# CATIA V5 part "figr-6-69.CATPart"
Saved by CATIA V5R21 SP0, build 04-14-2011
Part number: Part1
Bounding box of the stored display mesh (mm): x -44.666 to 106.759, y -69.79 to 69.79, z 0 to 74
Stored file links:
  D:\CATIA V5R21 E-RESOURCES\CATIA-V5R21\catia-v5r21-prt\c06-catia-v5r21-prt\c06-catia-v5r21-figr-6-69.CATPart
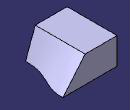
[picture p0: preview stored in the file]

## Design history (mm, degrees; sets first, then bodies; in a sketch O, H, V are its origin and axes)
Body1 (main body)
  Sketch1 on xy-plane, origin (0, 0, 0), H (1, 0, 0), V (0, 1, 0)
    line L1 (44.6658, 69.7903) -> (44.6658, -69.7903)
    line L2 (44.6658, -69.7903) -> (-44.6658, -69.7903)
    line L3 (-44.6658, -69.7903) -> (-44.6658, 69.7903)
    line L4 (-44.6658, 69.7903) -> (44.6658, 69.7903)
    vertical: L1 V, L3 V
    horizontal: L2 H, L4 H
    equidistance: L1 L3 O, L2 L4 O
  Pad1: profile Sketch1, direction (0, 0, 1), length 74
  Draft1: Angle 30, Neutral face of Pad1, PullDir face of Pad1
